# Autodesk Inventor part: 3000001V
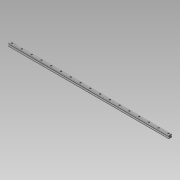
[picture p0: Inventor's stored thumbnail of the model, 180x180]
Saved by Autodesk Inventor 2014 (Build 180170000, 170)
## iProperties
Company: NHTSA/VRTC
Created: 2012-02
Part Number: 3000001V
Description: LINEAR RAIL - RAIL
Document SubType Name: Modeling
Designer: Dave Walker
Project: CHILD SIDE IMPACT SLED
Material: Stainless Steel
Stock Number: HSR30B128020 Rail
Mass: 6197.23 g
Surface Area: 1612.48 cm^2
Volume: 766.984 cm^3
Density: 8.08 g/cm^3
Appearance: Semi-Polished
NB: HSR30B128020 Rail
NN: Flange Type - Heavy Load HSR-B Rail
NBSYN: HSR30B128020 Rail
LINA: HSR30B128020 Rail
MN: HSR30B
NOB: 1
L: 280.0
GG: '', 'Symmetrical (G1=G2)', 'A', 'Asymmetrical'
GX: 20.00
GX1: 20
LMIN: 98.000
LEND: 8640.00
LMING: 8.00
LMAXG: 32.00
W1: 28.00
M1: 26.00
F: 80.00
D1: 9.00
D2: 14.00
HM: 12.00
MAXL: 3000.00
GMIN: 8.000
GMX: 20.000
GMAX1: 3.300
G1: 20.000
G2: 20.000
NX: 1.000
H3: 7.00
A: 4
LF: -20.000
LM: 320.000
LL: 620.000
AA: 3.000
GMAX: 32.000
P: 4.000
PX: 0.000
VG: 3.000
VGG: 20.000
VG1: -1.000
VG2: 4.000
ND: 4.000
LT: 2880.000
GA: 20.000
X: 0.000
KT: DUMMY
SUPPLIER: THK
ARTICLENO: HSR30B128020 Rail
BOMINFO: HSR30B128020 Rail
CREATOR: CADENAS GmbH
PSOL_IDENT_0: {\\10.0.0.251\ps_data\23d-libs\thk\linear_motion_systems\lm_guide\lm_guide\lm_guide_hsr\four_through
PSOL_IDENT_1: _hole_type\hsr_b\hsr_b_rail.prj},211 {VTYP=3D},{NB=HSR30B128020 Rail},{LINA=HSR30B128020 Rail},{NN=F
PSOL_IDENT_2: lange Type - Heavy Load HSR-B Rail},{DATE=04.07.2011 11:14:45},{GEOMDATE=04.07.2011 11:14:00},{VERSI
PSOL_IDENT_3: ON=},{LINEID=60},{LINESUBID=-1},{WBVAR=L,G,GX}  {NB=HSR30B128020 Rail},{LINA=HSR30B128020 Rail},{KT=
PSOL_IDENT_4: DUMMY},{MN=HSR30B},{NOB=1},{L=280.0},{G=},{GG='', 'Symmetrical (G1=G2)', 'A', 'Asymmetrical'},{GX=20
PSOL_IDENT_5: },{GX1=20},{LMIN=98},{LEND=8640.00},{LMING=8.00},{LMAXG=32.00},{W1=28.00},{M1=26.00},{F=80.00},{D1=9
PSOL_IDENT_6: .00},{D2=14.00},{HM=12.00},{MAXL=3000.00},{GMIN=8},{GMX=20},{GMAX1=3.3},{G1=20},{G2=20},{NX=1},{H3=7
PSOL_IDENT_7: .00},{A=4},{LF=-20},{LM=320},{LL=620},{AA=3},{GMAX=32},{P=4},{PX=0},{VG=3},{VGG=20},{VG1=-1},{VG2=4}
PSOL_IDENT_8: ,{ND=4.000},{LT=2880},{GA=20.000},{X=0.000}
Title: Linear Rail - Rail
Subject: Child Side Impact Sled
Author: Dave Walker
Comments: Reference Supplier: THK - http://www.thk.com/us/index.html Linear Rail System:  HSR-30B
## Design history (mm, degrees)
sketch "Sketch_16"
  geometry: L1 (-14, 22.215)-(-14, 19.779); L2 (-14, 19.779)-(-13.531, 19.31); L3 (-11, 16.779)-(-9.3, 15.079); L4 (-9.3, 15.079)-(-9.3, 11); L5 (-9.3, 11)-(-14, 6.3); L6 (-14, 6.3)-(-14, 1.5); L7 (-14, 1.5)-(-12.5, 0); L8 (-12.5, 0)-(-7.75, 0); L9 (-7.75, 0)-(-7.25, 0.5); L10 (-7.25, 0.5)-(-3.75, 0.5); L11 (-3.75, 0.5)-(-3.25, 0); L12 (-3.25, 0)-(3.25, 0); L13 (3.25, 0)-(3.75, 0.5); L14 (3.75, 0.5)-(7.25, 0.5); L15 (7.25, 0.5)-(7.75, 0); L16 (7.75, 0)-(12.5, 0); L17 (12.5, 0)-(14, 1.5); L18 (14, 1.5)-(14, 6.3); L19 (14, 6.3)-(9.3, 11); L20 (9.3, 11)-(9.3, 15.079); L21 (9.3, 15.079)-(11, 16.779); L22 (13.531, 19.31)-(14, 19.779); L23 (14, 19.779)-(14, 22.215); L24 (14, 22.215)-(13.525, 22.69); L25 (11, 25.215)-(10.215, 26); L26 (10.215, 26)-(-10.215, 26); L27 (-10.215, 26)-(-11, 25.215); L28 (-13.525, 22.69)-(-14, 22.215); A1 r 2.89 centre (-13.87, 16.44) between (-11, 16.779) and (-13.531, 19.31); A2 r 2.89 centre (13.87, 16.44) between (13.531, 19.31) and (11, 16.779); A3 r 2.89 centre (13.87, 25.56) between (11, 25.215) and (13.525, 22.69); A4 r 2.89 centre (-13.87, 25.56) between (-13.525, 22.69) and (-11, 25.215)
  constraints: 56 end point, 8 point on circle, 4 centre point
extrude "Extrusion1" new body sketch "Sketch_16" distance "d0" = 1314.45; taper "d1" = 0 deg
sketch "Sketch3"
  geometry: L1 (0, 0)-(0, -20.43) reference; L2 (0, -20.43)-(1314.45, -20.43) reference; L3 (0, 0)-(1314.45, 0) reference; 2 further points
  dimensions: "d9" = 20 distance from line of point (20, -10.215) L1; "d10" = 20.43001 distance between parallel lines of L2 L3 (derived); "d11" = 10.215 distance from line of point (20, -10.215) L3 (= 0.5 x d10)
hole "Hole1" sketch "Sketch3" at (20, -10.215) diameter "d12" = 9; stored, may be unused: countersink angle "d16" = 90 deg, drill point angle "d18" = 118 deg; dims "d13" = 6, "d14" = 14, "d15" = 12, "d17" = 8
body "Solid1"
pattern_linear "Rectangular Pattern2" dims "d21" = 80
